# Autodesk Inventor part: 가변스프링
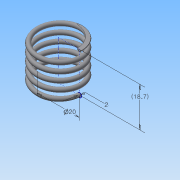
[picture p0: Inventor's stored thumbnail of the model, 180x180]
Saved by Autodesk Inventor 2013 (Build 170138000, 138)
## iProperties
Created: 2019-01
Part Number: 가변스프링
Material: 일반
Document SubType Name: Modeling
Designer: Gpr
Density: 1 g/cm^3
Mass: 0.965346 g
Surface Area: 19.6297 cm^2
Volume: 0.965346 cm^3
Author: Gpr
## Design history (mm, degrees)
sketch "스케치1"
  geometry: L1 (0, 0)-(10, 0); L2 (10, 0)-(10, 18.7); L3 (10, 18.7)-(0, 18.7); L4 (0, 18.7)-(0, 0); C1 r 1 at (10, 0)
  constraints: 8 end point, 2 parallel, 1 centre point, 1 coincident, 1 horizontal, 1 perpendicular
  dimensions: "d0" = 2 diameter of C1; "d1" = 20 diameter of L2 L4; "d2" = 18.7 distance between parallel lines of L3 L1 (derived)
feature "코일1" pitch "d3" = 10; turns "d5" = 5; dims "d4" = 18.7 (= d2), "d6" = 0, angle "d7" = 90 deg, angle "d8" = 90 deg, "d9" = 0, "d10" = 0
sketch "스케치2"
  geometry: L1 (-9, 0)-(-11, 0) reference; L2 (-9, 0)-(-11, 0) reference; 1 further point
  constraints: 2 horizontal alignment
extrude "돌출1" cut sketch "스케치2" stored distance "d11" = 10; taper "d12" = 0 deg
node "작업 평면1"
sketch "스케치3"
  geometry: L1 (9, 0)-(11, 0) reference; 1 further point
  constraints: 1 horizontal alignment
extrude "돌출2" cut sketch "스케치3" stored distance "d13" = 10; taper "d14" = 0 deg
node "솔리드1"
node "절단 모서리 투영1"
node "절단 모서리 투영2"
node "절단 모서리 투영3"
